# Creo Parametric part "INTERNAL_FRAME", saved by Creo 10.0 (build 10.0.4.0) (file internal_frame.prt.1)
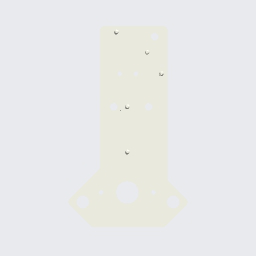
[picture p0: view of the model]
Units: millimeter Kilogram Sec (mmKs); MM, KILOGRAM, SECS

Created from: XX_SOLID_PART_MMKS_NEW_ABS.PRT

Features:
  1. datum plane "RIGHT"
  2. datum plane "TOP"
  3. datum plane "FRONT"
  4. coordinate system
  5. extrusion "Extrude 1"
  6. extrusion "Extrude 2"
  7. extrusion "Extrude 3"
  8. extruded cut "Extrude 4"
  9. extrusion "Extrude 5"
  10. extruded cut "Extrude 6"
  11. round "Round 1"
  12. extrusion "Extrude 7"
  13. extruded cut "Extrude 8"
  14. round "Round 2"
  15. round "Round 3"
  16. round "Round 4"
  17. chamfer "Chamfer 1"
  18. sketch "Sketch 1", "PNT0"
  19. sketch "Sketch 2", "PNT1"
